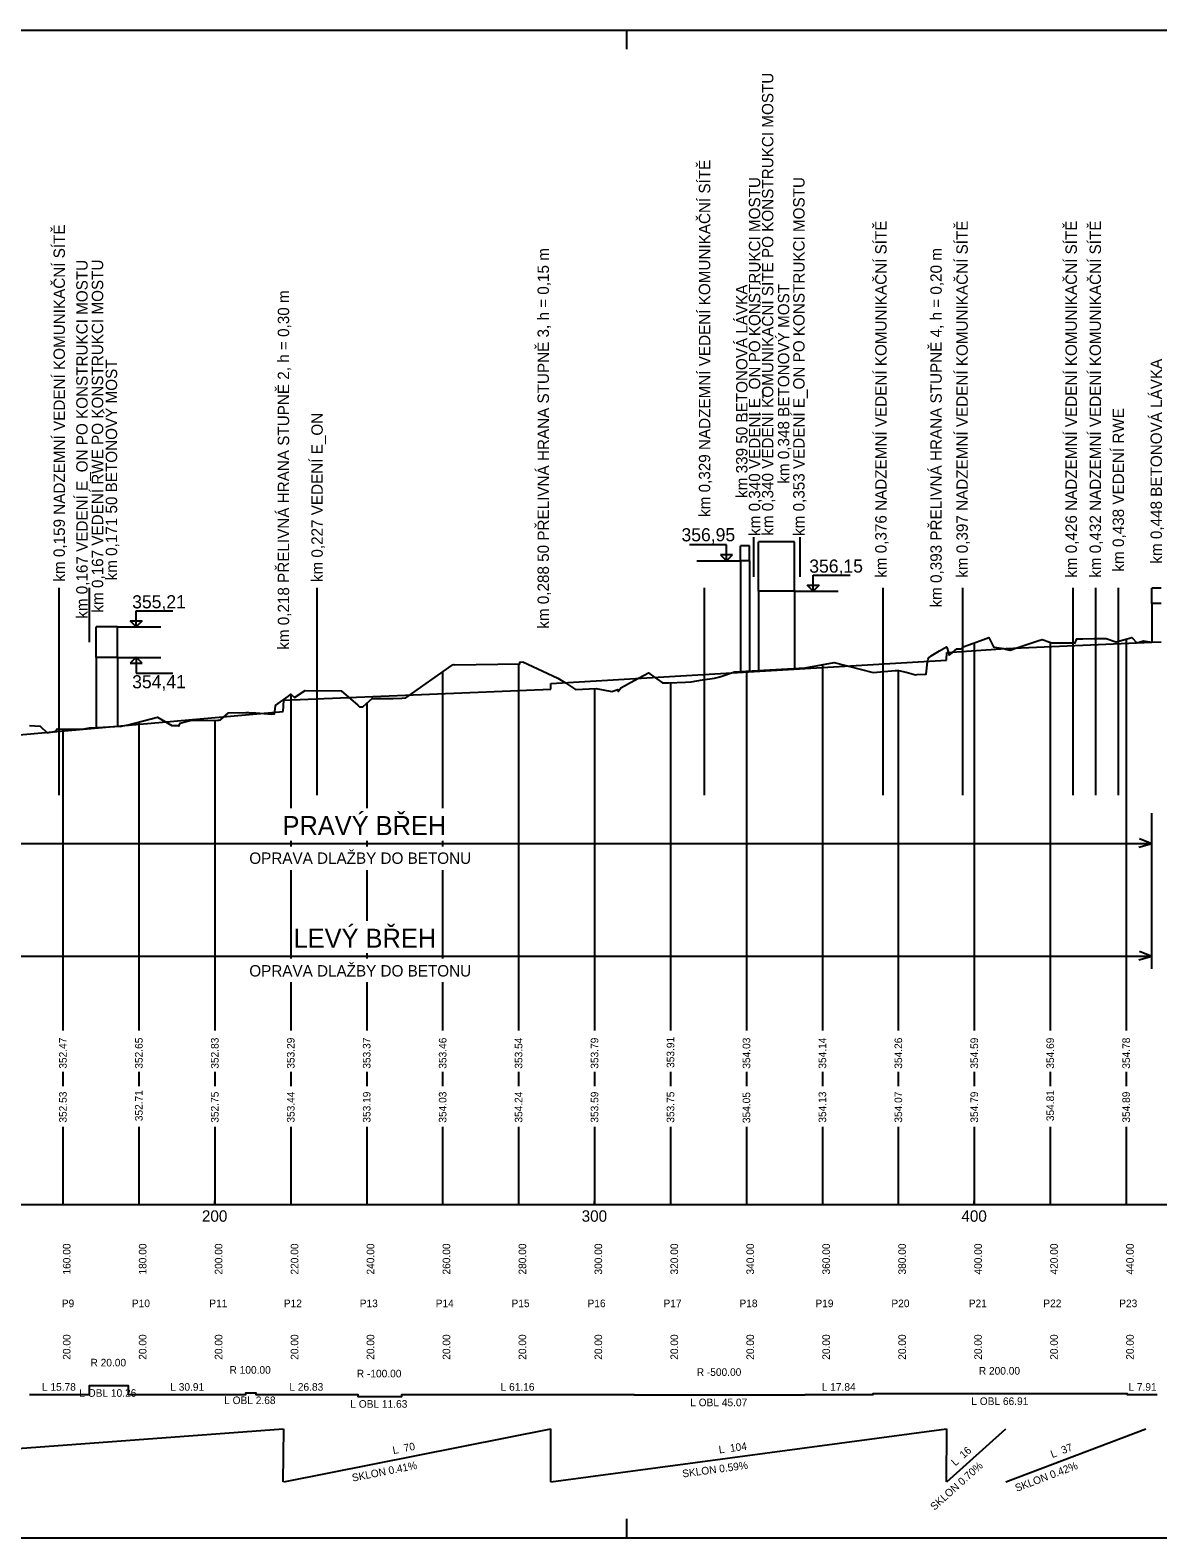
# Model space of a CAD drawing. Extents: x -590347 to -589507, y -1130318 to -1129921.
# Drawn here: x -590084.4 to -589787.4, y -1130318.2 to -1129921.2 of the extents above; entities that cross this region are included whole.
import ezdxf

# ---------------------------------------------------------------- set-up
doc = ezdxf.new("R2010")
doc.units = 0
for name, color, linetype in [('03_PC_NÁVRH_AS_H', 7, 'Continuous'), ('11', 7, 'Continuous'), ('13', 7, 'Continuous'), ('4', 7, 'Continuous'), ('56', 7, 'Continuous'), ('hraniceABH', 7, 'Continuous'), ('Vrstva 1', 7, 'Continuous'), ('Vrstva 4', 7, 'Continuous')]:
    doc.layers.add(name, color=color, linetype=linetype)

msp = doc.modelspace()

# ---------------------------------------------------------------- linework, layer by layer
for p, q in [((-589842.97, -1130085.13), (-589827.42, -1130084.03)), ((-589827.42, -1130084.03), (-589788.94, -1130082.41)), ((-589788.94, -1130082.41), (-589786.54, -1130082.31)), ((-589947.22, -1130093.25), (-589843.04, -1130087.13)), ((-589843.04, -1130087.13), (-589842.97, -1130085.13)), ((-590017.6, -1130097.63), (-589947.29, -1130094.76)), ((-589947.29, -1130094.76), (-589947.22, -1130093.25)), ((-590017.7, -1130100.63), (-590017.6, -1130097.63)), ((-590206.21, -1130117.28), (-590017.7, -1130100.63))]:
    msp.add_line(p, q)
for points in [[(-590084.55, -1130104.29), (-590081.74, -1130104.53), (-590079.89, -1130106.21), (-590078.05, -1130105.87), (-590077.76, -1130106.01), (-590077.28, -1130105.2), (-590070.69, -1130105.28), (-590068.77, -1130104.95), (-590068.37, -1130104.89), (-590068.32, -1130104.89), (-590060.46, -1130104.49), (-590060.44, -1130104.56), (-590060.43, -1130104.54), (-590060.38, -1130104.53), (-590059.45, -1130104.34), (-590058.51, -1130104.12), (-590050.82, -1130102.11), (-590047.04, -1130104.35), (-590045.4, -1130104.31), (-590045.17, -1130104.52), (-590044.9, -1130103.72), (-590042.18, -1130103.02), (-590034.92, -1130102.95), (-590034.61, -1130102.87), (-590034.27, -1130102.82), (-590034.21, -1130102.83), (-590032.14, -1130100.94), (-590027.6, -1130100.91), (-590026.78, -1130100.91), (-590024.92, -1130101.02), (-590020.72, -1130101.3), (-590020.06, -1130101.24), (-590019.75, -1130099.2), (-590019.68, -1130098.95), (-590016.37, -1130096.57), (-590015.7, -1130096.09), (-590015.7, -1130096.07), (-590014.73, -1130096.92), (-590011.95, -1130095.08), (-590002.45, -1130095.23), (-589998.09, -1130098.97), (-589997.61, -1130099.38), (-589996.98, -1130099.38), (-589996.76, -1130099.44), (-589995.76, -1130098.56), (-589994.32, -1130097.24), (-589993.44, -1130097.25), (-589991.11, -1130097.24), (-589988.78, -1130097.19), (-589986.46, -1130097.12), (-589985.4, -1130097.07), (-589973.27, -1130088.45), (-589973.18, -1130088.3), (-589972.83, -1130088.25), (-589972.68, -1130088.37), (-589955.44, -1130088.06), (-589955.38, -1130087.61), (-589954.6, -1130087.54), (-589945.43, -1130091.85), (-589943.42, -1130093.1), (-589940.72, -1130094.88), (-589935.33, -1130094.55), (-589931.15, -1130095.38), (-589929.6, -1130094.84), (-589929.55, -1130095.35), (-589928.85, -1130094.44), (-589925.3, -1130092.48), (-589921.57, -1130090.41), (-589920.79, -1130090.96), (-589917.84, -1130093.09), (-589916.28, -1130093.04), (-589911.77, -1130092.87), (-589910.33, -1130092.81), (-589907.27, -1130092.33), (-589904.12, -1130091.82), (-589903.78, -1130091.79), (-589902.76, -1130091.46), (-589898.91, -1130090.2), (-589880.23, -1130089.1), (-589872.61, -1130087.71), (-589862.39, -1130090.37), (-589862.36, -1130090.38), (-589859.48, -1130090.1), (-589856.57, -1130089.87), (-589855.67, -1130089.81), (-589853.66, -1130090.29), (-589851.19, -1130090.95), (-589850.75, -1130090.93), (-589848.43, -1130090.8), (-589848.08, -1130087.59), (-589847.85, -1130086.83), (-589847.76, -1130086.56), (-589847.1, -1130086.01), (-589844.94, -1130084.7), (-589843.08, -1130083.56), (-589842.87, -1130083.92), (-589842.35, -1130085.81), (-589842.03, -1130085.54), (-589840.33, -1130084.1), (-589839.18, -1130084.14), (-589839.12, -1130084.08), (-589838.65, -1130083.64), (-589836.21, -1130082.72), (-589833.3, -1130081.65), (-589831.91, -1130081.14), (-589830.66, -1130083.61), (-589830.39, -1130083.66), (-589827.97, -1130084.08), (-589827.48, -1130084.2), (-589826.41, -1130084.48), (-589826.4, -1130084.47), (-589826.32, -1130084.46), (-589824.57, -1130083.85), (-589821.66, -1130082.86), (-589818.75, -1130081.9), (-589817.9, -1130081.63), (-589815.85, -1130082.34), (-589815.2, -1130082.54), (-589812.94, -1130082.54), (-589810.03, -1130082.54), (-589809.13, -1130082.54), (-589808.71, -1130081.5), (-589807.12, -1130081.49), (-589804.21, -1130081.45), (-589801.3, -1130081.39), (-589801.02, -1130081.38), (-589798.46, -1130082.3), (-589798.39, -1130082.28), (-589795.48, -1130081.49), (-589794.28, -1130081.18), (-589792.91, -1130082.57), (-589791.18, -1130082.05), (-589788.94, -1130082.41)], [(-589835.74, -1130082.55), (-589835.74, -1130160.48), (-589835.74, -1130170.48), (-589835.74, -1130184.66)], [(-589815.74, -1130082.37), (-589815.74, -1130160.48), (-589815.74, -1130170.48), (-589815.74, -1130184.66)], [(-589795.74, -1130081.56), (-589795.74, -1130160.48), (-589795.74, -1130170.48), (-589795.74, -1130184.66)], [(-589955.74, -1130088.07), (-589955.74, -1130160.48), (-589955.74, -1130170.48), (-589955.74, -1130184.66)], [(-589875.74, -1130088.28), (-589875.74, -1130160.48), (-589875.74, -1130170.48), (-589875.74, -1130184.66)], [(-589975.74, -1130090.21), (-589975.74, -1130126.11)], [(-589895.74, -1130090.02), (-589895.74, -1130160.48), (-589895.74, -1130170.48), (-589895.74, -1130184.66)], [(-589855.74, -1130089.81), (-589855.74, -1130160.48), (-589855.74, -1130170.48), (-589855.74, -1130184.66)], [(-590015.74, -1130096.12), (-590015.74, -1130126.11)], [(-589935.74, -1130094.57), (-589935.74, -1130160.48), (-589935.74, -1130170.48), (-589935.74, -1130184.66)], [(-589915.74, -1130093.02), (-589915.74, -1130160.48), (-589915.74, -1130170.48), (-589915.74, -1130184.66)], [(-589995.74, -1130098.54), (-589995.74, -1130126.11)], [(-590055.74, -1130103.39), (-590055.74, -1130160.48), (-590055.74, -1130170.48), (-590055.74, -1130184.66)], [(-590035.74, -1130102.95), (-590035.74, -1130160.48), (-590035.74, -1130170.48), (-590035.74, -1130184.66)], [(-590075.74, -1130105.22), (-590075.74, -1130160.48), (-590075.74, -1130170.48), (-590075.74, -1130184.66)], [(-590015.74, -1130134.65), (-590015.74, -1130136.2)], [(-589995.74, -1130134.65), (-589995.74, -1130136.2)], [(-589975.74, -1130134.65), (-589975.74, -1130136.2)], [(-590015.74, -1130142.41), (-590015.74, -1130160.48), (-590015.74, -1130165.71)], [(-589995.74, -1130142.41), (-589995.74, -1130155.74)], [(-589975.74, -1130142.41), (-589975.74, -1130160.48), (-589975.74, -1130165.71)], [(-589995.74, -1130164.28), (-589995.74, -1130165.71)], [(-590015.74, -1130171.92), (-590015.74, -1130184.66)], [(-589995.74, -1130171.92), (-589995.74, -1130184.66)], [(-589975.74, -1130171.92), (-589975.74, -1130184.66)], [(-590075.74, -1130195.5), (-590075.74, -1130199.29)], [(-590055.74, -1130195.5), (-590055.74, -1130199.29)], [(-590035.74, -1130195.5), (-590035.74, -1130199.29)], [(-590015.74, -1130195.5), (-590015.74, -1130199.29)], [(-589995.74, -1130195.5), (-589995.74, -1130199.29)], [(-589975.74, -1130195.5), (-589975.74, -1130199.29)], [(-589955.74, -1130195.5), (-589955.74, -1130199.29)], [(-589935.74, -1130195.5), (-589935.74, -1130199.29)], [(-589915.74, -1130195.5), (-589915.74, -1130199.29)], [(-589895.74, -1130195.5), (-589895.74, -1130199.29)], [(-589875.74, -1130195.5), (-589875.74, -1130199.29)], [(-589855.74, -1130195.5), (-589855.74, -1130199.29)], [(-589835.74, -1130195.5), (-589835.74, -1130199.29)], [(-589815.74, -1130195.5), (-589815.74, -1130199.29)], [(-589795.74, -1130195.5), (-589795.74, -1130199.29)], [(-590075.74, -1130209.97), (-590075.74, -1130230.48)], [(-590055.74, -1130209.97), (-590055.74, -1130230.48)], [(-590035.74, -1130209.97), (-590035.74, -1130230.48)], [(-590015.74, -1130209.97), (-590015.74, -1130230.48)], [(-589995.74, -1130209.97), (-589995.74, -1130230.48)], [(-589975.74, -1130209.97), (-589975.74, -1130230.48)], [(-589955.74, -1130209.97), (-589955.74, -1130230.48)], [(-589935.74, -1130209.97), (-589935.74, -1130230.48)], [(-589915.74, -1130209.97), (-589915.74, -1130230.48)], [(-589895.74, -1130209.97), (-589895.74, -1130230.48)], [(-589875.74, -1130209.97), (-589875.74, -1130230.48)], [(-589855.74, -1130209.97), (-589855.74, -1130230.48)], [(-589835.74, -1130209.97), (-589835.74, -1130230.48)], [(-589815.74, -1130209.97), (-589815.74, -1130230.48)], [(-589795.74, -1130209.97), (-589795.74, -1130230.48)], [(-590084.55, -1130280.48), (-590068.77, -1130280.48), (-590068.77, -1130278.08), (-590058.51, -1130278.08), (-590058.51, -1130280.48), (-590027.6, -1130280.48), (-590027.6, -1130280), (-590024.92, -1130280), (-590024.92, -1130280.48), (-589998.09, -1130280.48), (-589998.09, -1130280.96), (-589986.46, -1130280.96), (-589986.46, -1130280.48), (-589925.3, -1130280.48), (-589925.3, -1130280.57), (-589880.23, -1130280.57), (-589880.23, -1130280.48), (-589862.39, -1130280.48), (-589862.39, -1130280.24), (-589795.48, -1130280.24), (-589795.48, -1130280.48), (-589787.57, -1130280.48)], [(-590206.21, -1130303.48), (-590017.7, -1130289.48)], [(-590017.7, -1130303.48), (-590017.6, -1130289.48)], [(-590017.6, -1130303.48), (-589947.29, -1130289.48)], [(-589947.29, -1130303.48), (-589947.22, -1130289.48)], [(-589947.22, -1130303.48), (-589843.04, -1130289.48)], [(-589843.04, -1130303.48), (-589842.97, -1130289.48)], [(-589842.97, -1130303.48), (-589827.42, -1130289.48)], [(-589827.42, -1130303.48), (-589790.55, -1130289.48)]]:
    msp.add_lwpolyline(points)
at = {"layer": '03_PC_NÁVRH_AS_H'}
for p, q in [((-589908.76, -1130060.98), (-589897.34, -1130060.98)), ((-589883.04, -1130068.98), (-589871.62, -1130068.98)), ((-590061.34, -1130078.38), (-590049.92, -1130078.38)), ((-590061.34, -1130086.38), (-590049.92, -1130086.38))]:
    msp.add_line(p, q, dxfattribs=at)
at = {"layer": '56'}
for p, q in [((-590235.74, -1130230.48), (-589735.74, -1130230.48)), ((-590035.74, -1130230.48), (-590035.74, -1130229.48)), ((-589935.74, -1130230.48), (-589935.74, -1130229.48)), ((-589835.74, -1130230.48), (-589835.74, -1130229.48))]:
    msp.add_line(p, q, dxfattribs=at)
at = {"layer": 'hraniceABH'}
for p, q in [((-590347.23, -1129921.22), (-589507.23, -1129921.22)), ((-589927.23, -1129926.22), (-589927.23, -1129921.22)), ((-589927.23, -1130318.22), (-589927.23, -1130313.22)), ((-590347.23, -1130318.22), (-589507.23, -1130318.22))]:
    msp.add_line(p, q, dxfattribs=at)
at = {"layer": 'Vrstva 1'}
for p, q in [((-589893.75, -1130065.14), (-589893.75, -1130054.74)), ((-589892.54, -1130068.98), (-589892.54, -1130055.98)), ((-589883.04, -1130055.98), (-589892.54, -1130055.98)), ((-589883.04, -1130068.98), (-589883.04, -1130055.98)), ((-589881.59, -1130065.14), (-589881.59, -1130054.74)), ((-589900.99, -1130056.75), (-589910.69, -1130056.73)), ((-589899.39, -1130059.38), (-589902.59, -1130059.38)), ((-589901.01, -1130060.98), (-589900.99, -1130056.75)), ((-589901.01, -1130060.98), (-589899.39, -1130059.38)), ((-589897.34, -1130060.98), (-589897.34, -1130056.98)), ((-589894.94, -1130056.98), (-589897.34, -1130056.98)), ((-589894.94, -1130060.98), (-589894.94, -1130056.98)), ((-589894.94, -1130060.98), (-589897.34, -1130060.98)), ((-589897.34, -1130060.98), (-589897.34, -1130090.32)), ((-589894.94, -1130060.98), (-589894.94, -1130090.18)), ((-590076.74, -1130122.69), (-590076.74, -1130068.06)), ((-590068.74, -1130082.38), (-590068.74, -1130068.06)), ((-590008.74, -1130122.69), (-590008.74, -1130068.06)), ((-589906.74, -1130122.69), (-589906.74, -1130068.06)), ((-589878.14, -1130068.98), (-589879.76, -1130067.38)), ((-589879.76, -1130067.38), (-589876.56, -1130067.38)), ((-589878.16, -1130064.75), (-589868.46, -1130064.73)), ((-589878.14, -1130068.98), (-589878.16, -1130064.75)), ((-589859.74, -1130122.69), (-589859.74, -1130068.06)), ((-589838.74, -1130122.69), (-589838.74, -1130068.06)), ((-589809.74, -1130122.69), (-589809.74, -1130068.06)), ((-589803.74, -1130122.69), (-589803.74, -1130068.06)), ((-589797.74, -1130122.69), (-589797.74, -1130068.06)), ((-589788.94, -1130072.18), (-589788.94, -1130068.18)), ((-589786.54, -1130068.18), (-589788.94, -1130068.18)), ((-589883.04, -1130068.98), (-589892.54, -1130068.98)), ((-589892.54, -1130068.98), (-589892.54, -1130090.04)), ((-589883.04, -1130068.98), (-589883.04, -1130089.48)), ((-589786.54, -1130072.18), (-589788.94, -1130072.18)), ((-589788.94, -1130072.18), (-589788.94, -1130082.41)), ((-590056.46, -1130074.15), (-590046.76, -1130074.13)), ((-590056.44, -1130078.38), (-590056.46, -1130074.15)), ((-590066.94, -1130086.38), (-590066.94, -1130078.38)), ((-590061.34, -1130078.38), (-590066.94, -1130078.38)), ((-590061.34, -1130086.38), (-590061.34, -1130078.38)), ((-590056.44, -1130078.38), (-590058.06, -1130076.78)), ((-590058.06, -1130076.78), (-590054.86, -1130076.78)), ((-590061.34, -1130086.38), (-590066.94, -1130086.38)), ((-590066.94, -1130086.38), (-590066.94, -1130104.98)), ((-590061.34, -1130086.38), (-590061.34, -1130104.49)), ((-590056.44, -1130086.28), (-590058.06, -1130087.88)), ((-590058.06, -1130087.88), (-590054.86, -1130087.88)), ((-590056.44, -1130086.28), (-590056.46, -1130090.51)), ((-590056.46, -1130090.51), (-590046.76, -1130090.53)), ((-589788.94, -1130168.41), (-589788.94, -1130127.36)), ((-590219.44, -1130135.35), (-589788.94, -1130135.35)), ((-589792.41, -1130136.37), (-589788.94, -1130135.35)), ((-589792.24, -1130134.04), (-589788.94, -1130135.35)), ((-589792.24, -1130163.71), (-589788.94, -1130165.02)), ((-590146.74, -1130165.02), (-589788.94, -1130165.02)), ((-589792.41, -1130166.04), (-589788.94, -1130165.02))]:
    msp.add_line(p, q, dxfattribs=at)
at = {"layer": 'Vrstva 4'}
for p, q in [((-589902.59, -1130059.38), (-589901.01, -1130060.98)), ((-589876.56, -1130067.38), (-589878.14, -1130068.98)), ((-590054.86, -1130076.78), (-590056.44, -1130078.38)), ((-590054.86, -1130087.88), (-590056.44, -1130086.28))]:
    msp.add_line(p, q, dxfattribs=at)

# ---------------------------------------------------------------- texts
msp.add_text('P100.00Vlevo', height=0.0035).set_placement((-589992.27, -1130256.48))
at = {"layer": '11'}
for s, height, rotation, p in [('km 0,340 VEDENÍ KOMUNIKAČNÍ SÍTĚ PO KONSTRUKCI MOSTU', 3, 90, (-589888.65, -1130054.35)), ('km 0,329 NADZEMNÍ VEDENÍ KOMUNIKAČNÍ SÍTĚ', 3, 90, (-589905.27, -1130049.4)), ('km 0,340 VEDENÍ E_ON PO KONSTRUKCI MOSTU', 3, 90, (-589892.1, -1130054.41)), ('km 0,353 VEDENÍ E_ON PO KONSTRUKCI MOSTU', 3, 90, (-589880.43, -1130054.41)), ('km 0,159 NADZEMNÍ VEDENÍ KOMUNIKAČNÍ SÍTĚ', 3, 90, (-590075.21, -1130066.44)), ('km 0,376 NADZEMNÍ VEDENÍ KOMUNIKAČNÍ SÍTĚ', 3, 90, (-589858.83, -1130065.43)), ('km 0,397 NADZEMNÍ VEDENÍ KOMUNIKAČNÍ SÍTĚ', 3, 90, (-589837.45, -1130065.43)), ('km 0,426 NADZEMNÍ VEDENÍ KOMUNIKAČNÍ SÍTĚ', 3, 90, (-589808.72, -1130065.43)), ('km 0,432 NADZEMNÍ VEDENÍ KOMUNIKAČNÍ SÍTĚ', 3, 90, (-589802.37, -1130065.43)), ('km 0,288 50 PŘELIVNÁ HRANA STUPNĚ 3, h = 0,15 m', 3, 90, (-589947.75, -1130078.84)), ('km 0,393 PŘELIVNÁ HRANA STUPNĚ 4, h = 0,20 m', 3, 90, (-589844.31, -1130073.25)), ('km 0,167 VEDENÍ E_ON PO KONSTRUKCI MOSTU', 3, 90, (-590069.22, -1130076.22)), ('km 0,167 VEDENÍ RWE PO KONSTRUKCI MOSTU', 3, 90, (-590065.13, -1130074.58)), ('km 339 50 BETONOVÁ LÁVKA', 3, 90, (-589895.47, -1130044.39)), ('km 0,348 BETONOVÝ MOST', 3, 90, (-589884.45, -1130040.66)), ('km 0,218 PŘELIVNÁ HRANA STUPNĚ 2, h = 0,30 m', 3, 90, (-590016.16, -1130084.38)), ('km 0,171 50 BETONOVÝ MOST', 3, 90, (-590061.46, -1130066.12)), ('km 0,448 BETONOVÁ LÁVKA', 3, 90, (-589786.32, -1130061.7)), ('km 0,227 VEDENÍ E_ON ', 3, 90, (-590007.31, -1130066.57)), ('km 0,438 VEDENÍ RWE', 3, 90, (-589796.31, -1130063.78)), ('OPRAVA DLAŽBY DO BETONU', 3, 360, (-590026.65, -1130140.75)), ('OPRAVA DLAŽBY DO BETONU', 3, 360, (-590026.65, -1130170.42)), ('352.47', 2, 90, (-590074.74, -1130194.69)), ('352.65', 2, 90, (-590054.74, -1130194.69)), ('352.83', 2, 90, (-590034.74, -1130194.69)), ('353.29', 2, 90, (-590014.74, -1130194.69)), ('353.37', 2, 90, (-589994.74, -1130194.69)), ('353.46', 2, 90, (-589974.74, -1130194.69)), ('353.54', 2, 90, (-589954.74, -1130194.68)), ('353.79', 2, 90, (-589934.74, -1130194.69)), ('353.91', 2, 90, (-589914.74, -1130194.49)), ('354.03', 2, 90, (-589894.74, -1130194.69)), ('354.14', 2, 90, (-589874.74, -1130194.68)), ('354.26', 2, 90, (-589854.74, -1130194.69)), ('354.59', 2, 90, (-589834.74, -1130194.69)), ('354.69', 2, 90, (-589814.74, -1130194.69)), ('354.78', 2, 90, (-589794.74, -1130194.69)), ('352.53', 2, 90, (-590074.74, -1130208.9)), ('352.71', 2, 90, (-590054.74, -1130208.51)), ('352.75', 2, 90, (-590034.74, -1130208.91)), ('353.44', 2, 90, (-590014.74, -1130208.89)), ('353.19', 2, 90, (-589994.74, -1130208.9)), ('354.03', 2, 90, (-589974.74, -1130208.9)), ('354.24', 2, 90, (-589954.74, -1130208.89)), ('353.59', 2, 90, (-589934.74, -1130208.9)), ('353.75', 2, 90, (-589914.74, -1130208.91)), ('354.05', 2, 90, (-589894.74, -1130209.02)), ('354.13', 2, 90, (-589874.74, -1130208.9)), ('354.07', 2, 90, (-589854.74, -1130208.9)), ('354.79', 2, 90, (-589834.74, -1130208.9)), ('354.81', 2, 90, (-589814.74, -1130208.51)), ('354.89', 2, 90, (-589794.74, -1130208.9)), ('160.00', 2, 90, (-590073.74, -1130248.89)), ('180.00', 2, 90, (-590053.74, -1130248.89)), ('200.00', 2, 90, (-590033.74, -1130248.89)), ('220.00', 2, 90, (-590013.74, -1130248.89)), ('240.00', 2, 90, (-589993.74, -1130248.89)), ('260.00', 2, 90, (-589973.74, -1130248.89)), ('280.00', 2, 90, (-589953.74, -1130248.89)), ('300.00', 2, 90, (-589933.74, -1130248.89)), ('320.00', 2, 90, (-589913.74, -1130248.89)), ('340.00', 2, 90, (-589893.74, -1130248.89)), ('360.00', 2, 90, (-589873.74, -1130248.89)), ('380.00', 2, 90, (-589853.74, -1130248.89)), ('400.00', 2, 90, (-589833.74, -1130248.89)), ('420.00', 2, 90, (-589813.74, -1130248.89)), ('440.00', 2, 90, (-589793.74, -1130248.89)), ('20.00', 2, 90, (-590073.74, -1130271.33)), ('20.00', 2, 90, (-590053.74, -1130271.33)), ('20.00', 2, 90, (-590033.74, -1130271.33)), ('20.00', 2, 90, (-590013.74, -1130271.33)), ('20.00', 2, 90, (-589993.74, -1130271.33)), ('20.00', 2, 90, (-589973.74, -1130271.33)), ('20.00', 2, 90, (-589953.74, -1130271.33)), ('20.00', 2, 90, (-589933.74, -1130271.33)), ('20.00', 2, 90, (-589913.74, -1130271.33)), ('20.00', 2, 90, (-589893.74, -1130271.33)), ('20.00', 2, 90, (-589873.74, -1130271.33)), ('20.00', 2, 90, (-589853.74, -1130271.33)), ('20.00', 2, 90, (-589833.74, -1130271.33)), ('20.00', 2, 90, (-589813.74, -1130271.33)), ('20.00', 2, 90, (-589793.74, -1130271.33)), ('L  70', 2, 11.2614, (-589988.7, -1130296.19)), ('L  104', 2, 7.6536, (-589902.89, -1130296.01)), ('L  16', 2, 41.9923, (-589840.72, -1130299.44)), ('L  37', 2, 20.7924, (-589815.2, -1130297.24)), ('SKLON 0.41%', 2, 11.2614, (-589999.41, -1130303.43)), ('SKLON 0.59%', 2, 7.6536, (-589912.5, -1130302.34)), ('SKLON 0.70%', 2, 41.9923, (-589846.23, -1130311.12)), ('SKLON 0.42%', 2, 20.7924, (-589824.56, -1130306.14))]:
    msp.add_text(s, height=height, rotation=rotation, dxfattribs=at).set_placement(p)
for s, p in [('P9', (-590076.03, -1130257.48)), ('P10', (-590057.57, -1130257.48)), ('P11', (-590037.19, -1130257.48)), ('P12', (-590017.56, -1130257.48)), ('P13', (-589997.58, -1130257.48)), ('P14', (-589977.57, -1130257.48)), ('P15', (-589957.6, -1130257.48)), ('P16', (-589937.58, -1130257.48)), ('P17', (-589917.58, -1130257.48)), ('P18', (-589897.58, -1130257.48)), ('P19', (-589877.58, -1130257.48)), ('P20', (-589857.57, -1130257.48)), ('P21', (-589837.19, -1130257.48)), ('P22', (-589817.56, -1130257.48)), ('P23', (-589797.58, -1130257.48)), ('R 20.00', (-590068.47, -1130273.08)), ('R 100.00', (-590031.86, -1130275)), ('R -100.00', (-589998.34, -1130275.96)), ('R -500.00', (-589908.83, -1130275.57)), ('R 200.00', (-589834.54, -1130275.24)), ('L 15.78', (-590081.26, -1130279.48)), ('L 30.91', (-590047.46, -1130279.48)), ('L 26.83', (-590016.1, -1130279.48)), ('L 61.16', (-589960.47, -1130279.48)), ('L 17.84', (-589875.9, -1130279.48)), ('L 7.91', (-589795.15, -1130279.48)), ('L OBL 10.26', (-590071.42, -1130281.08)), ('L OBL 2.68', (-590033.27, -1130283)), ('L OBL 11.63', (-590000.05, -1130283.96)), ('L OBL 45.07', (-589910.54, -1130283.57)), ('L OBL 66.91', (-589836.52, -1130283.24))]:
    msp.add_text(s, height=2, dxfattribs=at).set_placement(p)
at = {"layer": '13'}
for s, p in [('200', (-590039.13, -1130234.98)), ('300', (-589939.13, -1130234.98)), ('400', (-589839.13, -1130234.98))]:
    msp.add_text(s, height=3, dxfattribs=at).set_placement(p)
at = {"layer": '4'}
for s, p in [('PRAVÝ BŘEH', (-590017.9, -1130133.16)), ('LEVÝ BŘEH', (-590014.99, -1130162.83))]:
    msp.add_text(s, height=5, dxfattribs=at).set_placement(p)
at = {"layer": 'Vrstva 1'}
for s, p in [('356,95', (-589912.84, -1130055.83)), ('356,15', (-589879.19, -1130064.08)), ('355,21', (-590057.49, -1130073.48)), ('354,41', (-590057.49, -1130094.53))]:
    msp.add_text(s, height=3.456, rotation=0.1193, dxfattribs=at).set_placement(p)

doc.saveas('drawing.dxf')
